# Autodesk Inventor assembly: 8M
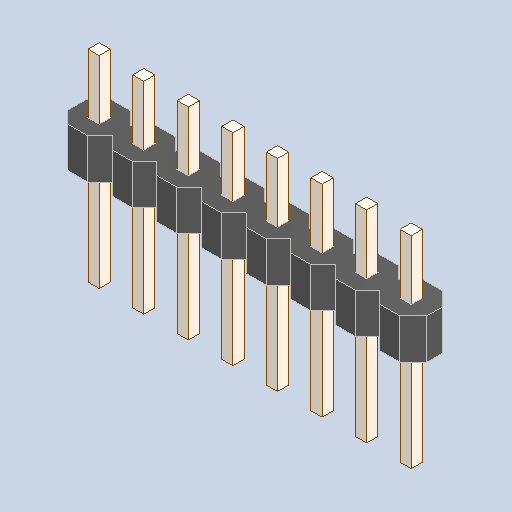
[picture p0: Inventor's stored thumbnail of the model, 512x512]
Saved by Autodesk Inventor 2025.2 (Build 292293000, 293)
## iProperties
Created: 2025-04
Part Number: 8M
Description: PART--DESC
Document SubType Name: Assembly
Designer: BennF
Author: BennF
Revision Number: NONE
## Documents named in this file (3)
- C:\Users\BennF\Nextcloud\Benutzer\CNC JarBeRi\existing parts\Electronics\RepRap A4988 Shied (USE WITHOUT ARDUINO)\reprap-a4988-1.snapshot.1\RepRap\RepRap\8M_5.iam
- C:\Users\BennF\Nextcloud\Benutzer\CNC JarBeRi\existing parts\Electronics\RepRap A4988 Shied (USE WITHOUT ARDUINO)\reprap-a4988-1.snapshot.1\RepRap\RepRap\8M Geometry.ipt
- C:\Users\BennF\Nextcloud\Benutzer\CNC JarBeRi\existing parts\Electronics\RepRap A4988 Shied (USE WITHOUT ARDUINO)\reprap-a4988-1.snapshot.1\RepRap\RepRap\pin4.ipt
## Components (2 placed, 2 different names)
1. 8M Geometry
2. pin4
